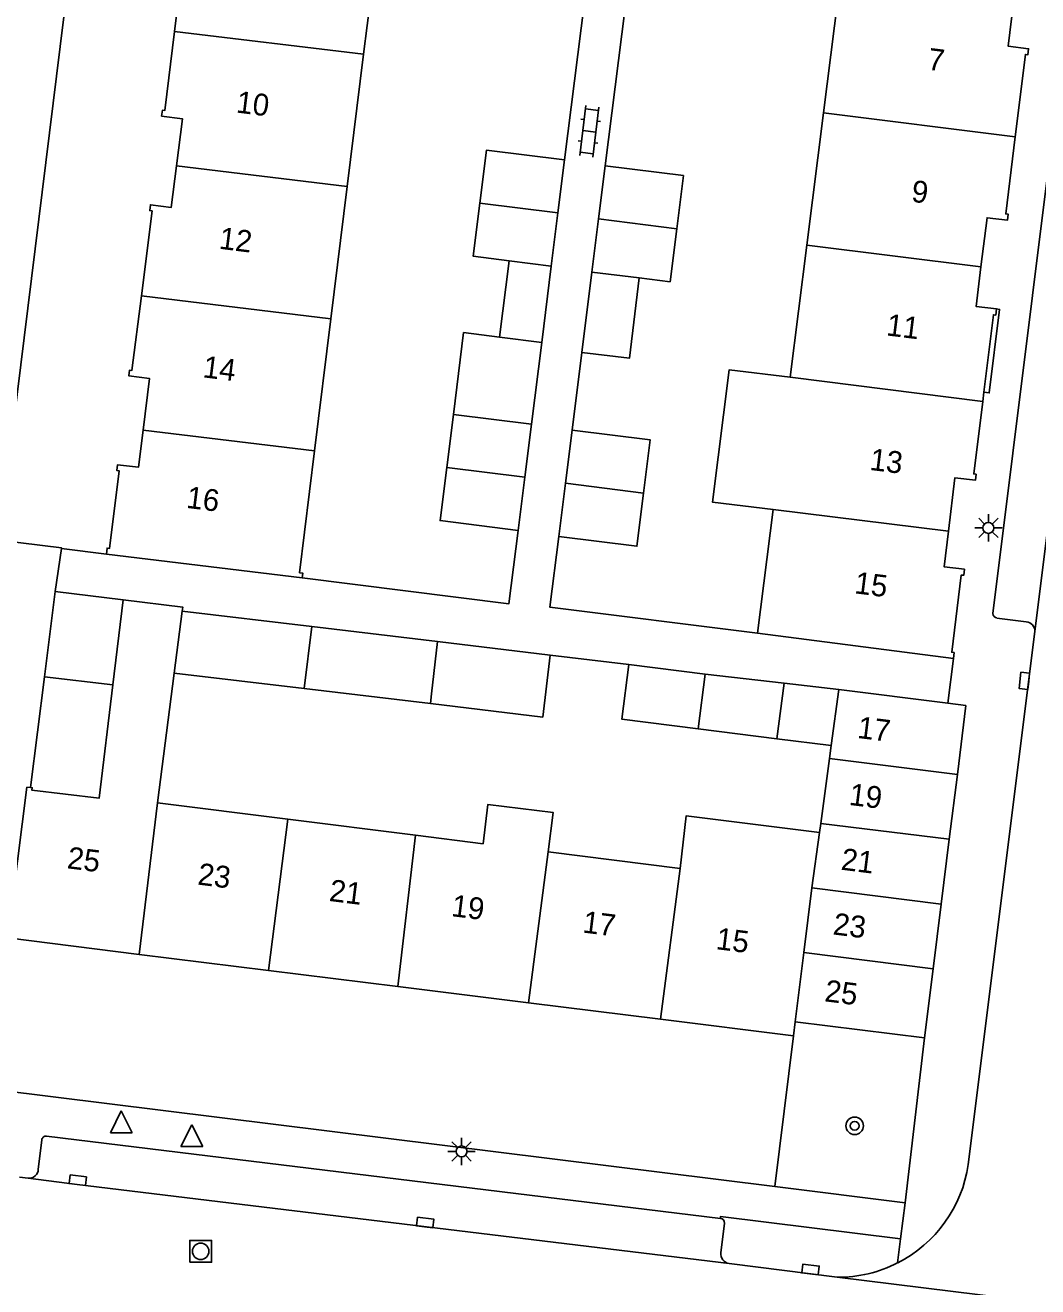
# Model space of a CAD drawing. Extents: x 131000 to 133014, y 396499 to 399001.
# Drawn here: x 131871.7 to 131918, y 397186.5 to 397244.2 of the extents above; entities that cross this region are included whole.
import ezdxf

# ---------------------------------------------------------------- set-up
doc = ezdxf.new("R2010")
doc.units = 0
for name, color, linetype in [('gg-afsc-erfafscheiding', 7, 'Continuous'), ('gg-afsc-muur', 7, 'Continuous'), ('gg-anno-huisnummerreeks BGT', 7, 'Continuous'), ('gg-bbg-bijgebouw', 7, 'Continuous'), ('gg-bbg-gedigitaliseerde bebouwing', 7, 'Continuous'), ('gg-bbg-gedigitaliseerde bijgebouw', 7, 'Continuous'), ('gg-bbg-hoofdgebouw', 7, 'Continuous'), ('gg-bbg-luifel en loopbrug', 7, 'Continuous'), ('gg-bbg-tussenscheiding', 7, 'Continuous'), ('gg-knt-verharding', 7, 'Continuous'), ('gg-knt-verharding nz', 7, 'Continuous'), ('gt-grn-weggrens', 7, 'Continuous'), ('gt-symb-boom', 7, 'Continuous'), ('gt-symb-klinker verharding', 7, 'Continuous'), ('gt-symb-kolk', 7, 'Continuous'), ('gt-symb-lichtmast', 7, 'Continuous'), ('gt-symb-rioolschacht', 7, 'Continuous'), ('gt-symb-waterafsluiter', 7, 'Continuous')]:
    doc.layers.add(name, color=color, linetype=linetype)

# ---------------------------------------------------------------- blocks, each defined once
blk = doc.blocks.new('gt0-KL1')
at = {"layer": 'gt-symb-klinker verharding'}
for p, q in [((-1.15, 0.3), (1.15, 0.3)), ((-1, -0.3), (-1, 0.3)), ((-0.5, 0.3), (-0.5, 0.45)), ((0, -0.3), (0, 0.3)), ((0.5, 0.3), (0.5, 0.45)), ((1, -0.3), (1, 0.3)), ((-1.15, -0.3), (1.15, -0.3)), ((-0.5, -0.45), (-0.5, -0.3)), ((0.5, -0.45), (0.5, -0.3))]:
    blk.add_line(p, q, dxfattribs=at)
blk = doc.blocks.new('gt0-LMAST')
at = {"layer": 'gt-symb-lichtmast'}
for p, q in [((-0.005, 0.246), (-0.005, 0.621)), ((-0.182, 0.173), (-0.447, 0.438)), ((0.172, 0.173), (0.437, 0.438)), ((-0.255, -0.004), (-0.63, -0.004)), ((-0.182, -0.181), (-0.447, -0.446)), ((-0.005, -0.254), (-0.005, -0.629)), ((0.437, -0.446), (0.172, -0.181)), ((0.245, -0.004), (0.62, -0.004))]:
    blk.add_line(p, q, dxfattribs=at)
blk.add_circle((-0.005, -0.004), 0.25, dxfattribs=at)
blk = doc.blocks.new('gt0-KOLK')
at = {"layer": 'gt-symb-kolk'}
blk.add_lwpolyline([(0, 0), (0.375, 0), (0.375, 0.4), (-0.375, 0.4), (-0.375, 0), (0, 0)], dxfattribs=at)
blk = doc.blocks.new('gt0-BOOM')
at = {"layer": 'gt-symb-boom'}
for radius in [0.4, 0.2]:
    blk.add_circle((0, 0), radius, dxfattribs=at)
blk = doc.blocks.new('gt0-RS')
at = {"layer": 'gt-symb-rioolschacht'}
blk.add_lwpolyline([(-0.5, -0.5), (0.5, -0.5), (0.5, 0.5), (-0.5, 0.5)], close=True, dxfattribs=at)
blk.add_circle((0, 0), 0.375, dxfattribs=at)
blk = doc.blocks.new('gt0-WAFSL')
at = {"layer": 'gt-symb-waterafsluiter'}
for p, q in [((-0.5, -0.333), (0, 0.667)), ((0, 0.667), (0.5, -0.333)), ((0.5, -0.333), (-0.5, -0.333))]:
    blk.add_line(p, q, dxfattribs=at)

msp = doc.modelspace()

# ---------------------------------------------------------------- linework, layer by layer
at = {"layer": 'gg-afsc-erfafscheiding'}
for p, q in [((131897.273, 397245.304), (131896.366, 397238.07)), ((131899.134, 397245.031), (131898.227, 397237.796)), ((131897.156, 397229.255), (131896.71, 397225.698)), ((131875.405, 397220.031), (131873.346, 397220.289)), ((131895.705, 397215.406), (131899.306, 397214.975))]:
    msp.add_line(p, q, dxfattribs=at)
for points in [[(131884.359, 397218.941), (131893.819, 397217.755), (131894.24, 397221.11)], [(131905.199, 397216.405), (131895.695, 397217.596), (131896.101, 397220.836)]]:
    msp.add_lwpolyline(points, dxfattribs=at)
at = {"layer": 'gg-afsc-muur'}
for p, q in [((131873.062, 397218.312), (131872.57, 397214.41)), ((131876.17, 397217.933), (131873.062, 397218.312))]:
    msp.add_line(p, q, dxfattribs=at)
at = {"layer": 'gg-bbg-bijgebouw'}
for p, q in [((131913.9, 397213.205), (131908.913, 397213.826)), ((131914.728, 397213.102), (131913.9, 397213.205)), ((131914.728, 397213.102), (131914.335, 397209.944)), ((131914.335, 397209.944), (131913.966, 397206.977)), ((131913.966, 397206.977), (131913.597, 397204.011)), ((131913.597, 397204.011), (131913.229, 397201.054)), ((131913.229, 397201.054), (131912.835, 397197.889)), ((131912.835, 397197.889), (131906.92, 397198.625))]:
    msp.add_line(p, q, dxfattribs=at)
at = {"layer": 'gg-bbg-gedigitaliseerde bebouwing'}
for p, q in [((131887.169, 397242.897), (131887.917, 397248.946)), ((131908.973, 397246.267), (131908.209, 397240.219)), ((131886.422, 397236.847), (131887.169, 397242.897)), ((131908.209, 397240.219), (131907.445, 397234.171)), ((131885.674, 397230.797), (131886.422, 397236.847)), ((131907.445, 397234.171), (131906.68, 397228.122)), ((131884.926, 397224.747), (131885.674, 397230.797)), ((131884.237, 397219.177), (131884.926, 397224.747)), ((131905.916, 397222.075), (131905.199, 397216.405)), ((131877.745, 397208.642), (131878.511, 397214.586)), ((131883.698, 397207.896), (131877.745, 397208.642)), ((131889.547, 397207.163), (131883.698, 397207.896)), ((131892.642, 397206.776), (131889.547, 397207.163)), ((131901.647, 397205.647), (131895.618, 397206.403))]:
    msp.add_line(p, q, dxfattribs=at)
for points in [[(131906.68, 397228.122), (131903.893, 397228.454), (131903.129, 397222.407), (131905.916, 397222.075)], [(131895.618, 397206.403), (131895.839, 397208.209), (131892.861, 397208.572), (131892.642, 397206.776)], [(131908.026, 397207.293), (131901.934, 397208.056), (131901.647, 397205.647)]]:
    msp.add_lwpolyline(points, dxfattribs=at)
at = {"layer": 'gg-bbg-gedigitaliseerde bijgebouw'}
for p, q in [((131896.061, 397235.639), (131896.366, 397238.07)), ((131898.227, 397237.796), (131897.922, 397235.365)), ((131896.061, 397235.639), (131895.756, 397233.208)), ((131897.617, 397232.934), (131897.922, 397235.365)), ((131895.756, 397233.208), (131893.833, 397233.449)), ((131897.617, 397232.934), (131899.777, 397232.663)), ((131891.277, 397226.42), (131890.972, 397223.989)), ((131894.849, 397225.972), (131891.277, 397226.42)), ((131894.544, 397223.541), (131894.849, 397225.972)), ((131896.71, 397225.698), (131896.406, 397223.267)), ((131894.544, 397223.541), (131894.24, 397221.11)), ((131896.101, 397220.836), (131896.406, 397223.267)), ((131878.875, 397217.42), (131884.805, 397216.71)), ((131890.553, 397216.022), (131884.805, 397216.71)), ((131895.705, 397215.406), (131890.553, 397216.022)), ((131902.801, 397214.526), (131899.306, 397214.975)), ((131884.449, 397213.876), (131878.511, 397214.586)), ((131906.404, 397214.126), (131902.801, 397214.526)), ((131906.075, 397211.567), (131906.404, 397214.126)), ((131890.234, 397213.184), (131884.449, 397213.876)), ((131908.913, 397213.826), (131908.566, 397211.271)), ((131902.477, 397212.03), (131906.075, 397211.567)), ((131908.566, 397211.271), (131908.485, 397210.674)), ((131908.485, 397210.674), (131908.082, 397207.701)), ((131908.082, 397207.701), (131908.026, 397207.293))]:
    msp.add_line(p, q, dxfattribs=at)
for points in [[(131896.366, 397238.07), (131892.794, 397238.517), (131892.489, 397236.086)], [(131898.227, 397237.796), (131901.799, 397237.348), (131901.494, 397234.917)], [(131893.833, 397233.449), (131892.184, 397233.655), (131892.489, 397236.086)], [(131899.777, 397232.663), (131901.19, 397232.486), (131901.494, 397234.917)], [(131896.71, 397225.698), (131900.282, 397225.25), (131899.978, 397222.819)], [(131894.24, 397221.11), (131890.667, 397221.558), (131890.972, 397223.989)], [(131896.101, 397220.836), (131899.673, 397220.388), (131899.978, 397222.819)], [(131890.234, 397213.184), (131895.365, 397212.57), (131895.705, 397215.406)], [(131899.306, 397214.975), (131898.985, 397212.478), (131902.477, 397212.03)]]:
    msp.add_lwpolyline(points, dxfattribs=at)
at = {"layer": 'gg-bbg-hoofdgebouw'}
for p, q in [((131915.546, 397227.436), (131915.494, 397227.016)), ((131884.359, 397218.941), (131875.405, 397220.031)), ((131876.17, 397217.933), (131875.698, 397214.038)), ((131914.154, 397215.245), (131905.199, 397216.405)), ((131870.89, 397202.46), (131871.761, 397209.368)), ((131871.761, 397209.368), (131871.932, 397209.347)), ((131876.903, 397201.711), (131870.89, 397202.46)), ((131882.828, 397200.972), (131876.903, 397201.711)), ((131888.731, 397200.237), (131882.828, 397200.972)), ((131894.721, 397199.49), (131888.731, 397200.237)), ((131900.75, 397198.739), (131894.721, 397199.49)), ((131906.84, 397197.98), (131900.75, 397198.739)), ((131906.92, 397198.625), (131906.84, 397197.98))]:
    msp.add_line(p, q, dxfattribs=at)
for points in [[(131878.522, 397243.938), (131878.981, 397247.631), (131878.872, 397247.644), (131878.905, 397247.912), (131879.858, 397247.794), (131880.093, 397249.889)], [(131916.908, 397245.271), (131916.661, 397243.269), (131917.594, 397243.154), (131917.56, 397242.876), (131917.451, 397242.889), (131916.986, 397239.117)], [(131878.611, 397237.788), (131878.884, 397239.952), (131877.932, 397240.072), (131877.965, 397240.34), (131878.074, 397240.326), (131878.522, 397243.938)], [(131916.986, 397239.117), (131916.551, 397235.594), (131916.66, 397235.581), (131916.626, 397235.303), (131915.693, 397235.418), (131915.416, 397233.17)], [(131877.005, 397231.842), (131877.495, 397235.733), (131877.386, 397235.747), (131877.42, 397236.015), (131878.372, 397235.895), (131878.611, 397237.788)], [(131915.416, 397233.17), (131915.193, 397231.359), (131916.126, 397231.244)], [(131877.085, 397225.692), (131877.384, 397228.057), (131876.432, 397228.177), (131876.466, 397228.445), (131876.575, 397228.431), (131877.005, 397231.842)], [(131916.126, 397231.244), (131916.092, 397230.966), (131915.983, 397230.979), (131915.546, 397227.436)], [(131915.494, 397227.016), (131915.084, 397223.694), (131915.193, 397223.681), (131915.159, 397223.403), (131914.226, 397223.518), (131913.925, 397221.07)], [(131875.405, 397220.031), (131875.439, 397220.299), (131875.548, 397220.286), (131875.993, 397223.837), (131875.884, 397223.851), (131875.918, 397224.119), (131876.871, 397223.999), (131877.085, 397225.692)], [(131913.925, 397221.07), (131913.725, 397219.449), (131914.658, 397219.334), (131914.624, 397219.056), (131914.515, 397219.069), (131914.079, 397215.537), (131914.188, 397215.523), (131914.154, 397215.245)], [(131884.237, 397219.177), (131884.386, 397219.159), (131884.359, 397218.941)], [(131878.875, 397217.42), (131878.897, 397217.603), (131876.17, 397217.933)], [(131875.698, 397214.038), (131875.071, 397208.856), (131871.995, 397209.222), (131872.009, 397209.337), (131871.932, 397209.347)]]:
    msp.add_lwpolyline(points, dxfattribs=at)
at = {"layer": 'gg-bbg-luifel en loopbrug'}
for p, q in [((131893.395, 397229.957), (131893.833, 397233.449)), ((131895.756, 397233.208), (131895.318, 397229.715)), ((131897.617, 397232.934), (131897.156, 397229.255)), ((131895.318, 397229.715), (131893.395, 397229.957)), ((131895.318, 397229.715), (131894.849, 397225.972)), ((131872.57, 397214.41), (131871.932, 397209.347)), ((131875.698, 397214.038), (131872.57, 397214.41)), ((131906.404, 397214.126), (131908.913, 397213.826)), ((131906.075, 397211.567), (131908.566, 397211.271))]:
    msp.add_line(p, q, dxfattribs=at)
for points in [[(131897.156, 397229.255), (131899.341, 397228.995), (131899.777, 397232.663)], [(131891.277, 397226.42), (131891.747, 397230.163), (131893.395, 397229.957)]]:
    msp.add_lwpolyline(points, dxfattribs=at)
at = {"layer": 'gg-bbg-tussenscheiding'}
for p, q in [((131878.522, 397243.938), (131887.169, 397242.897)), ((131916.986, 397239.117), (131908.209, 397240.219)), ((131878.611, 397237.788), (131886.422, 397236.847)), ((131896.061, 397235.639), (131892.489, 397236.086)), ((131901.494, 397234.917), (131897.922, 397235.365)), ((131915.416, 397233.17), (131907.445, 397234.171)), ((131877.005, 397231.842), (131885.674, 397230.797)), ((131915.494, 397227.016), (131906.68, 397228.122)), ((131877.085, 397225.692), (131884.926, 397224.747)), ((131894.544, 397223.541), (131890.972, 397223.989)), ((131899.978, 397222.819), (131896.406, 397223.267)), ((131913.925, 397221.07), (131905.916, 397222.075)), ((131878.875, 397217.42), (131878.571, 397215.054)), ((131884.805, 397216.71), (131884.449, 397213.876)), ((131890.553, 397216.022), (131890.281, 397213.63)), ((131878.571, 397215.054), (131878.511, 397214.586)), ((131902.801, 397214.526), (131902.477, 397212.03)), ((131890.281, 397213.63), (131890.234, 397213.184)), ((131914.335, 397209.944), (131908.485, 397210.674)), ((131877.745, 397208.642), (131876.903, 397201.711)), ((131883.698, 397207.896), (131882.828, 397200.972)), ((131908.026, 397207.293), (131907.681, 397204.748)), ((131913.966, 397206.977), (131908.082, 397207.701)), ((131889.547, 397207.163), (131888.731, 397200.237)), ((131895.618, 397206.403), (131894.721, 397199.49)), ((131901.647, 397205.647), (131900.75, 397198.739)), ((131907.681, 397204.748), (131907.314, 397201.791)), ((131913.597, 397204.011), (131907.681, 397204.748)), ((131907.314, 397201.791), (131906.92, 397198.625)), ((131913.229, 397201.054), (131907.314, 397201.791))]:
    msp.add_line(p, q, dxfattribs=at)
at = {"layer": 'gg-knt-verharding'}
for p, q in [((131915.963, 397217.315), (131918.691, 397239.204)), ((131917.49, 397216.931), (131916.147, 397217.103)), ((131914.833, 397192.091), (131917.877, 397216.48)), ((131906.84, 397197.98), (131905.98, 397191.09)), ((131912.835, 397197.889), (131911.95, 397190.348)), ((131905.98, 397191.09), (131869.95, 397195.57)), ((131872.671, 397193.388), (131903.494, 397189.626)), ((131872.288, 397191.878), (131872.455, 397193.208)), ((131871.424, 397191.519), (131871.82, 397191.467)), ((131911.95, 397190.348), (131905.98, 397191.09)), ((131903.679, 397189.411), (131903.519, 397188.059)), ((131911.604, 397187.593), (131911.741, 397188.689)), ((131903.894, 397187.559), (131908.841, 397186.933))]:
    msp.add_line(p, q, dxfattribs=at)
for points in [[(131876.42, 397268.58), (131870.49, 397220.67), (131873.35, 397220.32), (131873.346, 397220.289)], [(131916.126, 397231.244), (131916.265, 397231.227), (131915.794, 397227.406), (131915.546, 397227.436)], [(131911.741, 397188.689), (131903.506, 397189.718), (131903.494, 397189.626)]]:
    msp.add_lwpolyline(points, dxfattribs=at)
for centre, radius, start, end in [((131916.184, 397217.321), 0.221, 181.63325, 260.27778), ((131917.461, 397216.514), 0.418, 355.28457, 85.98076), ((131872.632, 397193.215), 0.177, 77.32323, 182.28791), ((131871.864, 397191.888), 0.424, 263.98291, 358.59663), ((131908.857, 397192.973), 6.041, 297.04945, 351.60334), ((131903.477, 397189.424), 0.202, 356.23043, 85.19126), ((131903.985, 397188.018), 0.468, 174.98417, 258.75562), ((131908.861, 397192.963), 6.03, 269.81119, 297.0579)]:
    msp.add_arc(centre, radius, start, end, dxfattribs=at)
at = {"layer": 'gg-knt-verharding nz'}
msp.add_line((131917.877, 397216.48), (131920.563, 397238.078), dxfattribs=at)
msp.add_lwpolyline([(131871.82, 397191.467), (131874.072, 397191.176), (131903.894, 397187.559)], dxfattribs=at)
at = {"layer": 'gt-grn-weggrens'}
for p, q in [((131873.062, 397218.312), (131873.346, 397220.289)), ((131914.154, 397215.245), (131913.9, 397213.205)), ((131911.95, 397190.348), (131911.741, 397188.689)), ((131908.841, 397186.933), (131923.488, 397185.128))]:
    msp.add_line(p, q, dxfattribs=at)

# ---------------------------------------------------------------- block references
at = {"layer": 'gt-symb-boom'}
msp.add_blockref('gt0-BOOM', (131909.638, 397193.867), dxfattribs=at)
at = {"layer": 'gt-symb-klinker verharding', "rotation": 82.98875025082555}
msp.add_blockref('gt0-KL1', (131897.498, 397239.375), dxfattribs=at)
at = {"layer": 'gt-symb-kolk'}
for p, rotation in [((131917.603, 397214.206), 84.00113167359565), ((131874.072, 397191.176), -6.997895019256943), ((131889.964, 397189.241), -6.9978950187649), ((131907.592, 397187.092), -6.9978950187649)]:
    msp.add_blockref('gt0-KOLK', p, dxfattribs=dict(at, rotation=rotation))
at = {"layer": 'gt-symb-lichtmast'}
for p in [(131915.758, 397221.228), (131891.661, 397192.698)]:
    msp.add_blockref('gt0-LMAST', p, dxfattribs=at)
at = {"layer": 'gt-symb-rioolschacht'}
msp.add_blockref('gt0-RS', (131879.718, 397188.123), dxfattribs=at)
at = {"layer": 'gt-symb-waterafsluiter'}
for p in [(131876.088, 397193.88), (131879.312, 397193.251)]:
    msp.add_blockref('gt0-WAFSL', p, dxfattribs=at)

# ---------------------------------------------------------------- texts
at = {"layer": 'gg-anno-huisnummerreeks BGT'}
for s, rotation, p in [('7', 353, (131912.944, 397242.2)), ('10', 352.9, (131881.31, 397240.237)), ('9', 352.9, (131912.198, 397236.157)), ('12', 352.8, (131880.525, 397234.005)), ('11', 353, (131911.054, 397230.038)), ('14', 352.8, (131879.784, 397228.121)), ('13', 353, (131910.294, 397223.882)), ('16', 352.9, (131879.03, 397222.147)), ('15', 352.9, (131909.598, 397218.237)), ('17', 352.9, (131909.729, 397211.617)), ('19', 352.9, (131909.348, 397208.554)), ('25', 352.9, (131873.576, 397205.653)), ('21', 352.9, (131908.979, 397205.588)), ('23', 352.9, (131879.547, 397204.908)), ('21', 352.9, (131885.565, 397204.158)), ('19', 352.9, (131891.154, 397203.462)), ('17', 352.9, (131897.158, 397202.714)), ('23', 352.9, (131908.611, 397202.626)), ('15', 352.9, (131903.259, 397201.953)), ('25', 352.9, (131908.23, 397199.566))]:
    msp.add_text(s, height=1, rotation=rotation, dxfattribs=at).set_placement(p)

doc.saveas('drawing.dxf')
